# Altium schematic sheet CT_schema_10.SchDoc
size 278 x 170 mm
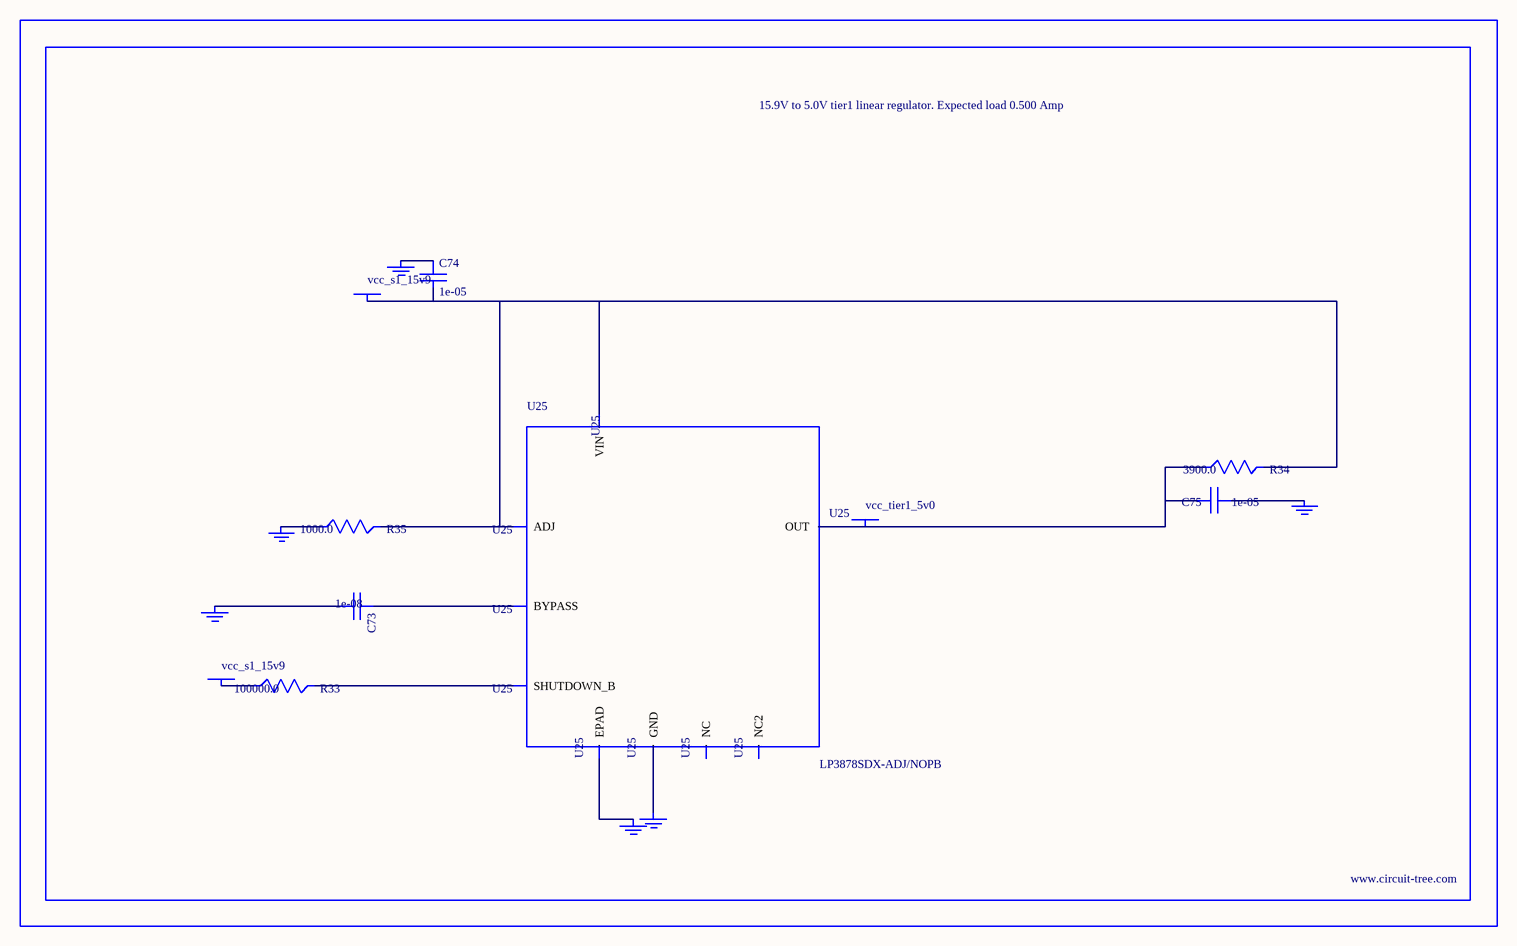
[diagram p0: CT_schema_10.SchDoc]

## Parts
BORDER9  (no value)
C73  1e-08  [C0402]
C74  1e-05  [C1210]
C75  1e-05  [C1210]
GND_INSTANCE_9_0  (no value)
GND_INSTANCE_9_1  (no value)
GND_INSTANCE_9_2  (no value)
GND_INSTANCE_9_3  (no value)
GND_INSTANCE_9_4  (no value)
GND_INSTANCE_9_5  (no value)
POWER_INSTANCE_9_0  vcc_s1_15v9
POWER_INSTANCE_9_1  vcc_s1_15v9
POWER_INSTANCE_9_2  vcc_tier1_5v0
R33  100000.0  [R0603]
R34  3900.0  [R0603]
R35  1000.0  [R0603]
U25  LP3878SDX-ADJ/NOPB  [WSON-8]

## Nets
NetC73_1: C73.1 U25.1(BYPASS)
NetC73_2: C73.2 GND_INSTANCE_9_0.0(GND)
NetC74_1: C74.1 GND_INSTANCE_9_1.0(GND)
NetC74_2: C74.2 POWER_INSTANCE_9_0.0(PWR) R34.2 R35.2 U25.4(VIN) U25.6(ADJ)
NetC75_1: C75.1 GND_INSTANCE_9_2.0(GND)
NetC75_2: C75.2 POWER_INSTANCE_9_2.0(PWR) R34.1 U25.5(OUT)
NetGND_INSTANCE_9_3_0: GND_INSTANCE_9_3.0(GND) R35.1
NetGND_INSTANCE_9_4_0: GND_INSTANCE_9_4.0(GND) U25.PAD(EPAD)
NetGND_INSTANCE_9_5_0: GND_INSTANCE_9_5.0(GND) U25.3(GND)
NetPOWER_INSTANCE_9_1_0: POWER_INSTANCE_9_1.0(PWR) R33.1
NetR33_2: R33.2 U25.8(SHUTDOWN_B)

Not connected (* = marked no-connect by the designer): U25 2(NC) 7(NC2)

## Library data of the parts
BORDER9 = BORDER_PAGE9
C73 = C0402C103K3RAC
C74 = C1210C106K5PACTU
C75 = GRM32DR61E106MA12L
GND_INSTANCE_9_0-GND_INSTANCE_9_5 = GND
POWER_INSTANCE_9_0-POWER_INSTANCE_9_2 = PWR
R33 = RC0603JR-07100KL
R34 = RC0603JR-073K9L
R35 = RC0603JR-071KL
